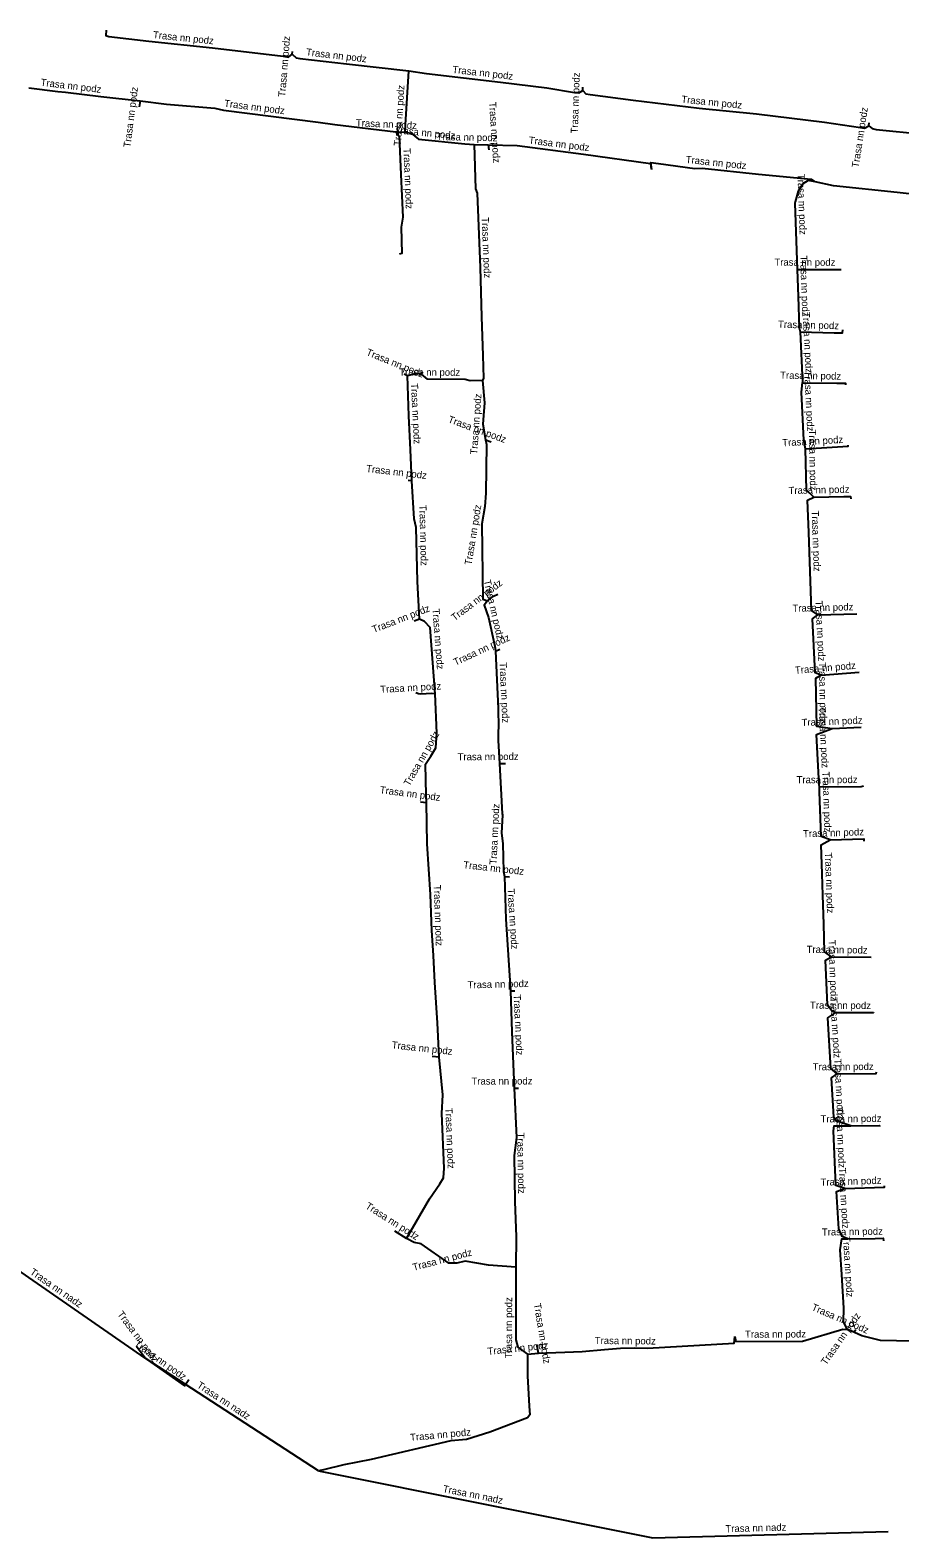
# Model space of a CAD drawing. Extents: x -724876 to -714160, y -1042389 to -1039790.
# Drawn here: x -715110.6 to -714988.8, y -1040737 to -1040525.7 of the extents above; entities that cross this region are included whole.
import ezdxf

# ---------------------------------------------------------------- set-up
doc = ezdxf.new("R2010")
doc.units = 0
doc.layers.add('Level 11', color=7, linetype='Continuous')
doc.layers.add('Level 20', color=7, linetype='Continuous')

msp = doc.modelspace()

# ---------------------------------------------------------------- linework, layer by layer
at = {"layer": 'Level 11'}
for p, q in [((-715073.89, -1040529.04), (-715073.86, -1040528.67)), ((-715033.2, -1040534.15), (-715033.18, -1040533.69)), ((-715095.23, -1040535.59), (-715095.34, -1040536.42)), ((-714993.12, -1040539.09), (-714993.06, -1040538.68)), ((-715048.42, -1040541.71), (-715046.43, -1040541.75)), ((-715046.43, -1040541.75), (-715046.38, -1040542.47)), ((-715003.15, -1040559.22), (-714996.97, -1040559.23)), ((-715002.76, -1040567.98), (-715002.39, -1040575.08)), ((-715057.75, -1040574.13), (-715058.23, -1040573.93)), ((-715046.83, -1040583.12), (-715046.02, -1040583.41)), ((-715057.16, -1040588.87), (-715057.66, -1040588.81)), ((-715000.24, -1040607.63), (-714994.78, -1040607.49)), ((-715056.05, -1040608.23), (-715056.84, -1040608.54)), ((-715045.44, -1040612.72), (-715044.81, -1040612.43)), ((-714999.78, -1040616.11), (-714994.46, -1040615.68)), ((-714998.26, -1040623.56), (-714994.18, -1040623.4)), ((-715044.86, -1040628.49), (-715044.02, -1040628.49)), ((-715055.1, -1040633.99), (-715055.92, -1040633.89)), ((-715044.14, -1040644.31), (-715043.44, -1040644.38)), ((-714998.33, -1040655.55), (-714992.78, -1040655.62)), ((-715043.32, -1040660.35), (-715042.71, -1040660.34)), ((-715053.31, -1040669.63), (-715054.29, -1040669.52)), ((-715042.79, -1040673.97), (-715042.21, -1040673.97)), ((-715057.89, -1040695.06), (-715059.52, -1040694.02)), ((-715094.5, -1040711.8), (-715117.2, -1040696.1)), ((-714995.21, -1040708.19), (-714994.95, -1040707.82)), ((-715094.5, -1040711.8), (-715095.7, -1040710.2)), ((-715040.92, -1040711.27), (-715039.42, -1040711.11)), ((-715039.42, -1040711.11), (-715039.63, -1040709.89)), ((-715070.2, -1040727.6), (-715094.5, -1040711.8)), ((-715070.2, -1040727.6), (-715023.4, -1040737)), ((-715023.4, -1040737), (-714990.4, -1040736.1))]:
    msp.add_line(p, q, dxfattribs=at)
for points in [[(-715099.96, -1040525.69), (-715100.01, -1040526.44), (-715099.6, -1040526.57), (-715093.98, -1040527.26), (-715085.07, -1040528.18), (-715075.17, -1040529.35), (-715074.42, -1040529.47), (-715073.89, -1040529.04)], [(-715073.89, -1040529.04), (-715073.35, -1040529.56), (-715072.82, -1040529.65), (-715066.29, -1040530.4), (-715057.55, -1040531.41)], [(-715058.09, -1040539.97), (-715058.01, -1040538.97), (-715057.55, -1040531.41)], [(-715057.55, -1040531.41), (-715055.07, -1040531.78), (-715044.71, -1040532.97), (-715038.23, -1040533.78), (-715034.36, -1040534.43), (-715033.77, -1040534.5), (-715033.2, -1040534.15)], [(-715110.79, -1040533.8), (-715106.74, -1040534.3), (-715105.65, -1040534.4), (-715100.7, -1040535), (-715095.23, -1040535.59)], [(-715095.23, -1040535.59), (-715091.52, -1040536.06), (-715084.76, -1040536.63), (-715083.54, -1040536.91), (-715070.29, -1040538.58), (-715067.93, -1040538.92), (-715059.41, -1040539.93)], [(-715033.2, -1040534.15), (-715032.76, -1040534.64), (-715032.16, -1040534.73), (-715026.12, -1040535.51), (-715016.87, -1040536.61), (-715008.85, -1040537.42), (-714999.33, -1040538.58), (-714994.3, -1040539.34), (-714993.7, -1040539.42), (-714993.12, -1040539.09)], [(-715059.41, -1040539.93), (-715058.95, -1040539.94), (-715058.09, -1040539.97)], [(-715059.41, -1040539.93), (-715058.91, -1040540.55), (-715058.68, -1040545.93), (-715058.43, -1040551.89), (-715058.63, -1040553.3), (-715058.57, -1040557), (-715058.89, -1040557.11)], [(-715058.09, -1040539.97), (-715057.26, -1040540.15), (-715056.19, -1040540.98), (-715049.7, -1040541.61), (-715048.42, -1040541.71)], [(-714993.12, -1040539.09), (-714992.65, -1040539.5), (-714992.08, -1040539.63), (-714985.52, -1040540.29), (-714977.52, -1040541.22), (-714970.11, -1040542.02), (-714962.07, -1040542.96), (-714962.02, -1040542.96)], [(-715048.42, -1040541.71), (-715048.22, -1040547.95), (-715047.99, -1040548.54), (-715047.59, -1040558.97), (-715047.38, -1040565.86), (-715047.22, -1040571.29), (-715047.11, -1040574.46), (-715047.23, -1040574.78)], [(-715046.43, -1040541.75), (-715042.4, -1040541.88), (-715033.08, -1040543.08), (-715023.71, -1040544.36), (-715023.59, -1040545.18)], [(-715023.54, -1040545.24), (-715023.68, -1040544.23), (-715022.57, -1040544.38), (-715017.48, -1040545.08), (-715016.49, -1040545.05), (-715008.57, -1040545.88), (-715001.21, -1040546.56), (-715000.62, -1040546.97)], [(-715000.62, -1040546.97), (-715001.63, -1040546.77), (-715002.36, -1040547.23), (-715003.03, -1040548.28), (-715003.45, -1040549.76), (-715003.47, -1040549.96), (-715003.15, -1040559.22)], [(-714961.49, -1040551.43), (-714975.27, -1040550), (-714989.13, -1040548.46), (-714998.06, -1040547.53), (-715000.62, -1040546.97)], [(-715003.15, -1040559.22), (-715003.04, -1040563.02), (-715002.88, -1040567.43), (-715002.76, -1040567.98)], [(-715002.76, -1040567.98), (-714997.97, -1040568.1), (-714996.8, -1040568.1), (-714996.77, -1040567.69)], [(-715047.23, -1040574.78), (-715048.98, -1040574.85), (-715049.68, -1040574.65), (-715054.97, -1040574.62), (-715055.8, -1040573.91), (-715055.96, -1040573.81), (-715056.67, -1040573.85), (-715057.75, -1040574.13)], [(-715057.16, -1040588.87), (-715057.32, -1040584.49), (-715057.56, -1040579.75), (-715057.75, -1040574.13)], [(-715047.23, -1040574.78), (-715046.97, -1040577.93), (-715047.18, -1040580.93), (-715046.83, -1040583.12)], [(-715001.97, -1040584.35), (-715002.2, -1040583.15), (-715002.53, -1040576.43), (-715002.39, -1040575.08)], [(-715002.39, -1040575.08), (-715002.3, -1040575.1), (-714997.58, -1040575.18), (-714996.39, -1040575.15), (-714996.37, -1040575.38)], [(-715046.83, -1040583.12), (-715046.7, -1040583.75), (-715046.77, -1040590.58), (-715046.92, -1040592.46), (-715047.32, -1040594.9), (-715047.18, -1040605.46), (-715046.53, -1040605.66)], [(-715001.97, -1040584.35), (-714996.74, -1040584.06), (-714996.01, -1040584.01), (-714996.01, -1040583.86)], [(-715000.8, -1040591.13), (-715001.86, -1040590.15), (-715001.97, -1040584.35)], [(-715056.05, -1040608.23), (-715056.33, -1040602.96), (-715056.52, -1040595.39), (-715056.82, -1040594.19), (-715057.16, -1040588.87)], [(-715000.24, -1040607.63), (-715001.15, -1040607.04), (-715001.53, -1040596.08), (-715001.72, -1040591.59), (-715000.8, -1040591.13)], [(-715000.8, -1040591.13), (-714996.61, -1040591.04), (-714995.67, -1040591.05), (-714995.64, -1040591.4)], [(-715046.53, -1040605.66), (-715047.03, -1040606.3), (-715046.42, -1040608.02), (-715045.51, -1040612.02), (-715045.44, -1040612.72)], [(-715046.53, -1040605.66), (-715045.72, -1040605.04), (-715045.09, -1040604.72)], [(-714999.78, -1040616.11), (-715000.62, -1040615.78), (-715000.99, -1040608.19), (-715000.24, -1040607.63)], [(-715053.86, -1040618.72), (-715054.57, -1040609.42), (-715055.39, -1040608.58), (-715056.05, -1040608.23)], [(-715045.44, -1040612.72), (-715045.07, -1040620.78), (-715045, -1040623.47), (-715045.05, -1040623.89), (-715045.04, -1040625.25), (-715044.86, -1040628.49)], [(-714999.78, -1040616.11), (-715000.57, -1040616.58), (-715000.45, -1040623.25), (-714998.26, -1040623.56)], [(-715053.86, -1040618.72), (-715054.34, -1040618.67), (-715055.91, -1040618.76), (-715056.19, -1040618.73), (-715056.58, -1040618.59)], [(-715055.1, -1040633.99), (-715055.15, -1040632.89), (-715055.23, -1040628.58), (-715054.47, -1040627.45), (-715053.79, -1040626.27), (-715053.64, -1040624.24), (-715053.86, -1040618.72)], [(-715000.05, -1040631.73), (-715000.07, -1040631.48), (-715000.46, -1040624.43), (-714998.26, -1040623.56)], [(-715044.86, -1040628.49), (-715044.49, -1040635.52), (-715044.45, -1040635.67), (-715044.57, -1040638.23), (-715044.41, -1040639.68), (-715044.3, -1040643.63), (-715044.14, -1040644.31)], [(-715000.05, -1040631.73), (-714994.21, -1040631.72), (-714993.87, -1040631.59)], [(-714998.52, -1040639.19), (-714999.81, -1040638.69), (-715000.03, -1040632.46), (-715000.05, -1040631.73)], [(-715053.31, -1040669.63), (-715053.56, -1040664.83), (-715053.9, -1040659.15), (-715054.09, -1040655.39), (-715054.35, -1040651.88), (-715054.53, -1040646.83), (-715054.98, -1040639.74), (-715055.1, -1040633.99)], [(-714998.33, -1040655.55), (-714999.31, -1040654.86), (-714999.43, -1040651), (-714999.57, -1040646.92), (-714999.66, -1040643.94), (-714999.78, -1040639.89), (-714998.52, -1040639.19)], [(-714998.52, -1040639.19), (-714993.84, -1040639.03), (-714993.83, -1040639.36)], [(-715044.14, -1040644.31), (-715043.98, -1040650.27), (-715043.32, -1040660.35)], [(-714997.74, -1040663.36), (-714998.27, -1040663.22), (-714998.93, -1040662.31), (-714999.17, -1040656.05), (-714998.33, -1040655.55)], [(-715043.32, -1040660.35), (-715043.15, -1040666.08), (-715042.79, -1040673.97)], [(-714997.56, -1040671.96), (-714998.44, -1040671.2), (-714998.87, -1040664.13), (-714997.74, -1040663.36)], [(-714997.74, -1040663.36), (-714992.47, -1040663.39), (-714992.41, -1040663.41)], [(-715057.89, -1040695.06), (-715054.67, -1040689.49), (-715053.22, -1040687.38), (-715052.72, -1040686.53), (-715052.62, -1040685.21), (-715052.93, -1040677.55), (-715052.79, -1040674.91), (-715053.31, -1040669.63)], [(-714995.66, -1040679.25), (-714997.74, -1040678.57), (-714998.02, -1040678.04), (-714998.33, -1040672.53), (-714997.56, -1040671.96)], [(-714997.56, -1040671.96), (-714992.07, -1040671.93), (-714992.06, -1040671.69)], [(-715042.79, -1040673.97), (-715042.49, -1040680.88), (-715042.83, -1040683.41), (-715042.73, -1040689.84), (-715042.54, -1040694.8), (-715042.58, -1040699.08)], [(-714996.47, -1040688.05), (-714997.73, -1040687.63), (-714998.08, -1040679.97), (-714997.95, -1040679.27), (-714995.66, -1040679.25)], [(-714995.66, -1040679.25), (-714991.64, -1040679.21), (-714991.66, -1040679.33)], [(-714926.72, -1040679.39), (-714926.75, -1040679.41), (-714939.25, -1040686.98), (-714953.19, -1040695.17), (-714955.6, -1040696.65), (-714966.92, -1040703.6), (-714975.16, -1040707.28), (-714980.69, -1040708.58), (-714987, -1040709.45), (-714991.48, -1040709.35), (-714994.09, -1040708.71), (-714995.13, -1040708.24), (-714995.21, -1040708.19)], [(-714996.05, -1040695.09), (-714996.86, -1040694.75), (-714997.33, -1040693.71), (-714997.64, -1040688.47), (-714996.47, -1040688.05)], [(-714996.47, -1040688.05), (-714990.9, -1040687.87), (-714990.91, -1040687.65)], [(-715042.58, -1040699.08), (-715046.42, -1040698.77), (-715049.65, -1040698.2), (-715050.86, -1040698.52), (-715051.98, -1040698.48), (-715055.84, -1040695.8), (-715056.83, -1040695.62), (-715057.89, -1040695.06)], [(-714996.1, -1040707.8), (-714996.66, -1040706.74), (-714996.63, -1040704.8), (-714996.92, -1040700.08), (-714997.14, -1040696.63), (-714996.92, -1040695.1), (-714996.05, -1040695.09)], [(-714996.05, -1040695.09), (-714992.22, -1040695.03), (-714991.1, -1040695.02), (-714991.07, -1040695.38)], [(-715042.58, -1040699.08), (-715042.59, -1040709.27), (-715042.29, -1040710.28), (-715040.92, -1040711.27)], [(-715039.42, -1040711.11), (-715033.28, -1040710.86), (-715030.17, -1040710.62), (-715027.9, -1040710.43), (-715026.01, -1040710.38), (-715024.15, -1040710.4), (-715011.99, -1040709.72), (-715011.91, -1040708.78)], [(-715011.9, -1040708.77), (-715011.77, -1040709.48), (-715002.42, -1040709.42), (-714996.75, -1040707.73), (-714996.1, -1040707.8)], [(-714995.21, -1040708.19), (-714995.3, -1040708.15), (-714996.1, -1040707.8)], [(-715040.92, -1040711.27), (-715040.94, -1040714.29), (-715040.7, -1040718.54), (-715040.62, -1040719.78), (-715040.92, -1040720.17), (-715046.2, -1040722.21), (-715049.5, -1040723.21), (-715051.69, -1040723.41), (-715062.83, -1040726.03), (-715066.66, -1040726.77), (-715069.54, -1040727.49), (-715070.2, -1040727.6)], [(-715094.5, -1040711.8), (-715089, -1040715.7), (-715088.4, -1040714.8)]]:
    msp.add_lwpolyline(points, dxfattribs=at)

# ---------------------------------------------------------------- texts
at = {"layer": 'Level 20'}
for s, rotation, p in [('Trasa nn podz', 354.1068, (-715093.45, -1040526.81)), ('Trasa nn podz', 85.3013, (-715074.89, -1040535.08)), ('Trasa nn podz', 353.3755, (-715072.01, -1040529.23)), ('Trasa nn podz', 353.4281, (-715051.5, -1040531.68)), ('Trasa nn podz', 88.1323, (-715033.89, -1040540.19)), ('Trasa nn podz', 353.0988, (-715109.2, -1040533.47)), ('Trasa nn podz', 82.7308, (-715096.58, -1040542.18)), ('Trasa nn podz', 86.5407, (-715058.69, -1040541.94)), ('Trasa nn podz', 352.8281, (-715083.49, -1040536.42)), ('Trasa nn podz', 273.9204, (-715046.33, -1040535.8)), ('Trasa nn podz', 354.2653, (-715019.42, -1040535.85)), ('Trasa nn podz', 357.3585, (-715065, -1040539.16)), ('Trasa nn podz', 81.2643, (-714994.54, -1040545.02)), ('Trasa nn podz', 354.3996, (-715059.61, -1040540.14)), ('Trasa nn podz', 358.8209, (-715053.7, -1040541.1)), ('Trasa nn podz', 272.3528, (-715058.33, -1040542.25)), ('Trasa nn podz', 352.6956, (-715040.81, -1040541.58)), ('Trasa nn podz', 354.0174, (-715018.81, -1040544.3)), ('Trasa nn podz', 271.9792, (-715003.11, -1040545.85)), ('Trasa nn podz', 272.2353, (-715047.36, -1040551.93)), ('Trasa nn podz', 272.0778, (-715002.75, -1040557.31)), ('Trasa nn podz', 359.9073, (-715006.35, -1040558.71)), ('Trasa nn podz', 272.9831, (-715002.4, -1040565.23)), ('Trasa nn podz', 358.5649, (-715005.85, -1040567.4)), ('Trasa nn podz', 337.9931, (-715063.63, -1040571.21)), ('Trasa nn podz', 359.6642, (-715058.92, -1040574.1)), ('Trasa nn podz', 359.029, (-715005.55, -1040574.54)), ('Trasa nn podz', 272.8114, (-715002.18, -1040573.42)), ('Trasa nn podz', 272.8088, (-715057.28, -1040575.19)), ('Trasa nn podz', 86.0175, (-715047.98, -1040585.2)), ('Trasa nn podz', 339.8471, (-715052.16, -1040580.63)), ('Trasa nn podz', 3.2315, (-715005.22, -1040584.03)), ('Trasa nn podz', 271.0865, (-715001.52, -1040581.68)), ('Trasa nn podz', 353.2434, (-715063.59, -1040587.6)), ('Trasa nn podz', 1.2305, (-715004.36, -1040590.71)), ('Trasa nn podz', 271.4455, (-715056.1, -1040592.23)), ('Trasa nn podz', 80.6365, (-715048.79, -1040600.72)), ('Trasa nn podz', 271.9857, (-715001.13, -1040593.04)), ('Trasa nn podz', 37.3294, (-715051.15, -1040608.55)), ('Trasa nn podz', 282.8291, (-715047.09, -1040602.84)), ('Trasa nn podz', 1.4688, (-715003.81, -1040607.22)), ('Trasa nn podz', 272.7909, (-715000.61, -1040605.66)), ('Trasa nn podz', 21.1348, (-715062.49, -1040610.19)), ('Trasa nn podz', 274.3591, (-715054.27, -1040606.81)), ('Trasa nn podz', 25.0915, (-715051.03, -1040614.79)), ('Trasa nn podz', 272.6226, (-715044.86, -1040614.3)), ('Trasa nn podz', 4.621, (-715003.43, -1040615.9)), ('Trasa nn podz', 271.0307, (-715000.11, -1040614.27)), ('Trasa nn podz', 3.3321, (-715061.54, -1040618.59)), ('Trasa nn podz', 273.1663, (-715000.17, -1040620.59)), ('Trasa nn podz', 2.2592, (-715002.52, -1040623.23)), ('Trasa nn podz', 60.229, (-715057.49, -1040631.73)), ('Trasa nn podz', 0.3386, (-715050.73, -1040628.03)), ('Trasa nn podz', 0.1177, (-715003.24, -1040631.24)), ('Trasa nn podz', 272.0224, (-714999.63, -1040629.6)), ('Trasa nn podz', 352.5806, (-715061.68, -1040632.63)), ('Trasa nn podz', 87.2535, (-715045.28, -1040642.66)), ('Trasa nn podz', 1.9581, (-715002.32, -1040638.82)), ('Trasa nn podz', 271.9653, (-714999.27, -1040640.95)), ('Trasa nn podz', 353.5701, (-715049.98, -1040643.14)), ('Trasa nn podz', 272.0179, (-715054.08, -1040645.52)), ('Trasa nn podz', 273.7839, (-715043.76, -1040646.03)), ('Trasa nn podz', 359.2774, (-715001.84, -1040655.01)), ('Trasa nn podz', 272.1956, (-714998.78, -1040653.23)), ('Trasa nn podz', 1.4156, (-715049.31, -1040660)), ('Trasa nn podz', 272.6283, (-715042.89, -1040660.86)), ('Trasa nn podz', 359.6738, (-715001.36, -1040662.84)), ('Trasa nn podz', 273.4805, (-714998.54, -1040661.26)), ('Trasa nn podz', 353.7372, (-715060, -1040668.39)), ('Trasa nn podz', 0.3131, (-715000.98, -1040671.48)), ('Trasa nn podz', 273.2201, (-714997.98, -1040669.89)), ('Trasa nn podz', 0.2003, (-715048.79, -1040673.49)), ('Trasa nn podz', 272.3396, (-715052.46, -1040676.75)), ('Trasa nn podz', 0.5421, (-714999.88, -1040678.79)), ('Trasa nn podz', 272.6161, (-714997.73, -1040676.66)), ('Trasa nn podz', 270.9534, (-715042.39, -1040680.22)), ('Trasa nn podz', 273.3857, (-714997.33, -1040685.17)), ('Trasa nn podz', 1.8509, (-714999.87, -1040687.66)), ('Trasa nn podz', 327.5311, (-715063.74, -1040690.74)), ('Trasa nn podz', 0.8522, (-714999.69, -1040694.64)), ('Trasa nn podz', 14.7155, (-715056.89, -1040699.58)), ('Trasa nn podz', 273.5159, (-714996.75, -1040694.77)), ('Trasa nn nadz', 325.3311, (-715110.74, -1040699.96)), ('Trasa nn podz', 306.8699, (-715098.47, -1040705.67)), ('Trasa nn podz', 89.9156, (-715043.1, -1040711.83)), ('Trasa nn podz', 279.3866, (-715040.06, -1040704.22)), ('Trasa nn podz', 336.6813, (-715001.23, -1040705.04)), ('Trasa nn podz', 54.9978, (-714999.1, -1040712.87)), ('Trasa nn podz', 324.6599, (-715096.15, -1040710.02)), ('Trasa nn podz', 6.017, (-715046.48, -1040711.36)), ('Trasa nn podz', 359.4775, (-715031.52, -1040709.83)), ('Trasa nn podz', 0.3677, (-715010.46, -1040708.97)), ('Trasa nn nadz', 326.9728, (-715087.35, -1040715.85)), ('Trasa nn podz', 5.2675, (-715057.34, -1040723.43)), ('Trasa nn nadz', 348.6395, (-715052.87, -1040730.57)), ('Trasa nn nadz', 1.5622, (-715013.2, -1040736.22))]:
    msp.add_text(s, height=1, rotation=rotation, dxfattribs=at).set_placement(p)

doc.saveas('drawing.dxf')
